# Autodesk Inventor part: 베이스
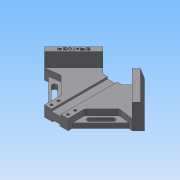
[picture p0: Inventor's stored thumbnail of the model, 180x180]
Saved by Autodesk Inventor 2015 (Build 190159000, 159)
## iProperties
Created: 2020-05
Part Number: 베이스
Material: 알루미늄 6061
Document SubType Name: Modeling
Designer: LINEART-SSD.D4.16.06
Density: 2.7 g/cm^3
Appearance: 기본값
Mass: 571.622 g
Surface Area: 407.173 cm^2
Volume: 211.712 cm^3
Author: LINEART-SSD.D4.16.06
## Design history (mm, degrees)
sketch "스케치1"
  geometry: L1 (0, 84.853)-(84.853, 0); L2 (84.853, 0)-(0, -84.853); L3 (0, -84.853)-(-84.853, 0); L4 (-84.853, 0)-(0, 84.853); L5 (0, 84.853)-(0, -84.853); L6 (84.853, 0)-(-84.853, 0); L7 (0, 84.853)-(120, 84.853); 1 further point
  constraints: 14 end point, 2 midpoint, 2 parallel, 1 equal length, 1 horizontal, 1 perpendicular
  dimensions: "d0" = 120 distance of L1.start L1.end; "d1" = 45 deg angle of L1 L7; "d2" = 120 distance of L1.end L2.end
extrude "돌출1" new body sketch "스케치1" stored distance "d3" = 42; taper "d4" = 0 deg
sketch "스케치2"
  geometry: L1 (-20, -84.853)-(20, -84.853); L2 (20, -84.853)-(20, -64.853); L3 (20, -64.853)-(-20, -64.853); L4 (-20, -64.853)-(-20, -84.853); L5 (0, -84.853)-(84.853, 0) reference; L6 (-84.853, 0)-(0, -84.853) reference; 1 further point
  constraints: 8 end point, 2 parallel, 2 point on line, 1 horizontal, 1 midpoint, 1 perpendicular
  dimensions: "d5" = 20 distance of L1.end L2.end
extrude "돌출2" cut sketch "스케치2" stored distance "d6" = 42; taper "d7" = 0 deg
sketch "스케치3"
  geometry: L1 (-35.355, 49.497)-(-24.749, 38.891); L2 (-16.005, 30.147)-(0, 30.147); L3 (0, 30.147)-(0, 84.853); L4 (0, 84.853)-(-35.355, 49.497); L5 (0, 84.853)-(-84.853, 0) reference; L6 (-20, -64.853)-(20, -64.853) reference; L7 (-24.749, 38.891)-(-74.246, -10.607); L8 (-74.246, -10.607)-(-20, -64.853); L9 (-20, -64.853)-(0, -64.853); L10 (0, -64.853)-(0, 30.147); L11 (-84.853, 0)-(-20, -64.853) reference; L12 (-24.749, 38.891)-(-16.005, 30.147); L13 (84.853, 0)-(0, 84.853) reference; L14 (20, -64.853)-(0, -64.853); L15 (74.246, -10.607)-(20, -64.853); L16 (24.749, 38.891)-(74.246, -10.607); L17 (16.005, 30.147)-(0, 30.147); L18 (24.749, 38.891)-(16.005, 30.147); L19 (35.355, 49.497)-(24.749, 38.891); L20 (0, 84.853)-(35.355, 49.497); 1 further point
  constraints: 32 end point, 5 perpendicular, 5 symmetric about line, 2 collinear, 2 horizontal, 1 midpoint
  dimensions: "d8" = 95 distance between parallel lines of L6 L2; "d9" = 15 distance between parallel lines of L5 L7; "d10" = 50 distance between parallel lines of L13 L1
extrude "돌출3" cut sketch "스케치3" distance "d11" = 24; taper "d12" = 0 deg
extrude "돌출4" cut sketch "스케치3" stored distance "d13" = 24; taper "d14" = 0 deg
sketch "스케치4"
  geometry: L1 (-74.246, -10.607)-(-68.059, -9.723); L2 (-49.497, -7.071)-(-20, -36.569); L3 (-20, -36.569)-(-20, -57.782); L4 (-20, -64.853)-(-74.246, -10.607); L5 (-68.059, -9.723)-(-20, -57.782); L6 (-20, -57.782)-(-20, -64.853); L7 (-68.059, -9.723)-(-49.497, -7.071); L8 (-20, -64.853)-(-74.246, -10.607) reference; L9 (-35.355, 49.497)-(-84.853, 0) reference; L10 (-84.853, 0)-(-74.246, -10.607) reference; 1 further point
  constraints: 14 end point, 2 collinear, 2 parallel, 2 vertical
  dimensions: "d15" = 30 distance from line of L2.start L9; "d16" = 5 distance between parallel lines of L5 L4; "d17" = 20 distance from line of point (0, 0) L6; "d18" = 20 distance between parallel lines of L10 L2
extrude "돌출5" cut sketch "스케치4" stored distance "d19" = 24; taper "d20" = 0 deg
extrude "돌출6" cut sketch "스케치4" distance "d21" = 10; taper "d22" = 0 deg
sketch "스케치5"
  geometry: L1 (-49.497, -18.385)-(-29.698, -38.184); L2 (-52.326, -21.213)-(-32.527, -41.012); L3 (-26.87, -35.355)-(-46.669, -15.556); L4 (-20, -57.782)-(-68.059, -9.723) reference; L5 (-84.853, 0)-(-74.246, -10.607) reference; L6 (-35.355, 49.497)-(-84.853, 0) reference; A1 r 4 centre (-49.497, -18.385) between (-46.669, -15.556) and (-52.326, -21.213); A2 r 4 centre (-29.698, -38.184) between (-32.527, -41.012) and (-26.87, -35.355); 2 further points
  constraints: 8 end point, 4 point on circle, 4 tangent, 2 centre point, 2 parallel, 1 midpoint
  dimensions: "d23" = 12 distance between parallel lines of L1 L5; "d24" = 28 distance of L1.start L1.end; "d25" = 38 distance from line of L6 L1.start; "d26" = 8 distance between parallel lines of L3 L2
extrude "돌출7" cut sketch "스케치5" stored distance "d27" = 10; taper "d28" = 0 deg
fillet "모깎기1" dims "d29" = 5
sketch "스케치7"
  geometry: L1 (20, 64.853)-(-20, 64.853) reference; 3 further points
  constraints: 1 vertical alignment
  dimensions: "d33" = 12 distance of point (-14, 46.853) point (-14, 58.853); "d34" = 6 distance from line of L1 point (-14, 58.853); "d35" = 14 horizontal distance of point (0, 0) point (-14, 58.853)
hole "구멍1" sketch "스케치7" at (-14, 58.853), (-14, 46.853) diameter "d36" = 4.5; stored, may be unused: countersink angle "d40" = 90 deg, drill point angle "d42" = 118 deg; dims "d37" = 6, "d38" = 8, "d39" = 10, "d41" = 8
sketch "스케치8"
  geometry: L1 (40, 18)-(0, 18) reference; L2 (40, 0)-(0, 0) reference; L3 (12, 18)-(28, 18); L4 (28, 18)-(28, 14.5); L5 (28, 14.5)-(12, 14.5); L6 (12, 14.5)-(12, 18); L7 (14, 3)-(26, 3); L8 (26, 3)-(26, 0); L9 (26, 0)-(14, 0); L10 (14, 0)-(14, 3); 3 further points
  constraints: 16 end point, 4 midpoint, 4 parallel, 2 horizontal, 2 perpendicular
  dimensions: "d43" = 16 distance between parallel lines of L4 L6; "d44" = 3.5 distance of L3.end L4.end; "d45" = 12 distance between parallel lines of L8 L10; "d46" = 3 distance of L7.end L8.end
extrude "돌출8" cut sketch "스케치8" stored distance "d47" = 10; taper "d48" = 0 deg
chamfer "모따기1" distance "d49" = 5; stored, may be unused: second distance "d50" = 15, angle "d51" = 45 deg
chamfer "모따기2" distance "d52" = 5; stored, may be unused: second distance "d53" = 15, angle "d54" = 45 deg
sketch "스케치9"
  geometry: L1 (-74.246, -10.607)-(-24.749, 38.891) reference; L2 (-24.749, 38.891)-(-31.82, 45.962) reference; L3 (-35.355, 49.497)-(-84.853, 0) reference; 2 further points
  constraints: 1 other
  dimensions: "d55" = 35 distance from line of L2 point (-53.033, 17.678); "d57" = 5 distance from line of L1 point (-53.033, 17.678)
feature "엠보싱1" sketch "스케치9" dims "d58" = 0.5, "d59" = 0
fillet "모깎기2" dims "d60" = 5
node "솔리드1"
mirror "대칭1"
